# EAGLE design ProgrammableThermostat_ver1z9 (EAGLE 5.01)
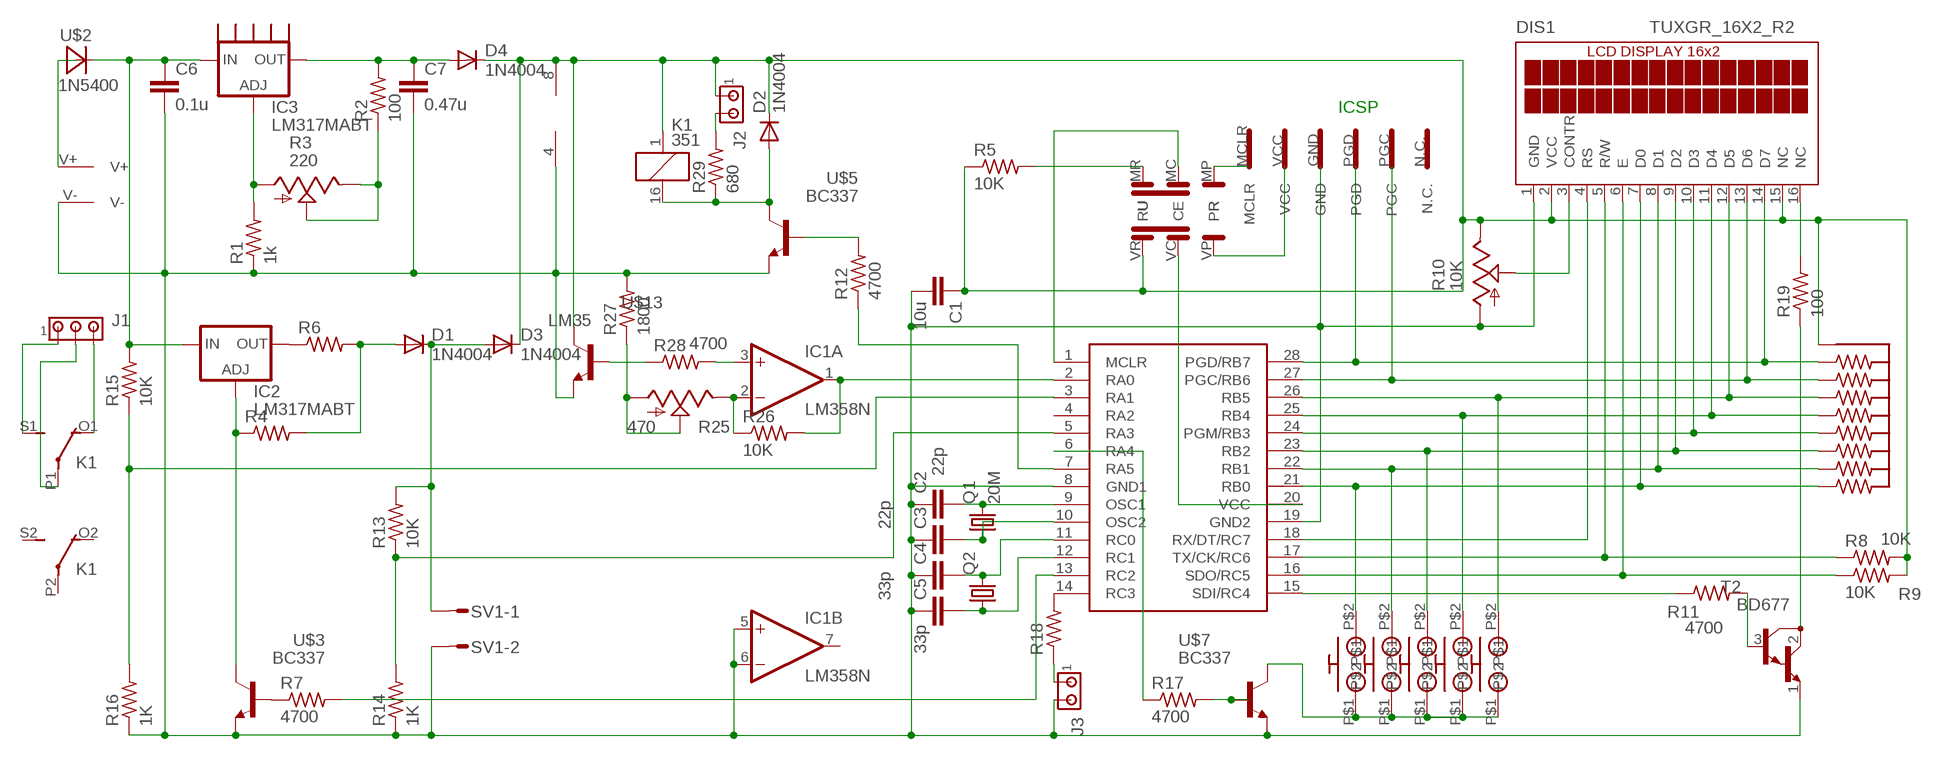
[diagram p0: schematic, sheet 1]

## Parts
C1  10u  C-EU025-050X050  [C025-050X050]
C2  22p  C-EU025-024X044  [C025-024X044]
C3  22p  C-EU025-024X044  [C025-024X044]
C4  33p  C-EU025-024X044  [C025-024X044]
C5  33p  C-EU025-024X044  [C025-024X044]
C6  0.1u  C-EU050-050X075  [C050-050X075]
C7  0.47u  C-EU050-050X075  [C050-050X075]
D1  1N4004  [DO41-10]
D2  1N4004  [DO41-10]
D3  1N4004  [DO41-10]
D4  1N4004  [DO41-10]
DIS1  TUXGR_16X2_R2  [TUXGR_16X2_R2]
IC1  LM358N  [DIL08]
IC2  LM317MABT  [TO220L1]
IC3  LM317MABT  [TO220L1]
J1  MTA03-156  [1X3MTA]
J2  MTA02-100  [10X02MTA]
J3  MTA02-100  [10X02MTA]
K1  351  [351]
Q1  20M  CRYSTALHC49U-V  [HC49U-V]
Q2  CRYSTALTC38H  [TC38H]
R1  1k  R-US_0207/7  [0207/7]
R2  100  R-US_0207/7  [0207/7]
R3  220  TRIM_US-CA9V  [CA9V]
R4  R-US_0207/7  [0207/7]
R5  10K  R-US_0207/7  [0207/7]
R6  R-US_0411/15  [0411/15]
R7  4700  R-US_0207/7  [0207/7]
R8  10K  R-US_0207/7  [0207/7]
R9  10K  R-US_0207/7  [0207/7]
R10  10K  TRIM_US-CA9V  [CA9V]
R11  4700  R-US_0207/7  [0207/7]
R12  4700  R-US_0207/7  [0207/7]
R13  10K  R-US_0207/7  [0207/7]
R14  1K  R-US_0207/7  [0207/7]
R15  10K  R-US_0207/7  [0207/7]
R16  1K  R-US_0207/7  [0207/7]
R17  4700  R-US_0207/7  [0207/7]
R18  R-US_0207/7  [0207/7]
R19  100  R-US_0207/7  [0207/7]
R25  470  TRIM_US-CA9V  [CA9V]
R26  10K  R-US_0207/7  [0207/7]
R27  1800  R-US_0207/7  [0207/7]
R28  4700  R-US_0207/7  [0207/7]
R29  680  R-US_0207/7  [0207/7]
SV1  L02P  [L02P]
T2  BD677  [TO126]
U$1  16F876A  [DIP28]
U$2  1N5400  [DO210-15]
U$3  BC337  [TO92]
U$4  SKHH  [SKHH]
U$5  BC337  [TO92]
U$6  POWER_SUPPLY  [POWER_SUPPLY]
U$7  BC337  [TO92]
U$8  SKHH  [SKHH]
U$9  HEATSINK1  [HEATSINK1]
U$10  SKHH  [SKHH]
U$11  SKHH  [SKHH]
U$12  SKHH  [SKHH]
U$13  LM35  BC337  [TO92]
U$14  ICSP  [ICSP]
U$15  ICSPSW  [ICSPSW]
U$16  RESISTIVE_NETWORK  [RESISTIVE_NETWORK_8X]

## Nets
GND: C1.2 C2.1 C3.1 C4.1 C5.1 C6.2 C7.2 DIS1.1(GND) IC1.4(P:V-) IC1.5(B:+IN) IC1.6(B:-IN) J3.2 R1.1 R10.A R14.1 R16.1 R27.2 SV1.2 T2.1(E) U$1.8(GND1) U$1.19(GND2) U$3.1(E) U$5.1(E) U$6.V- U$7.1(E) U$13.1(E) U$14.GND
N$1: R18.2 U$1.14(RC3)
N$2: C4.2 Q2.2 U$1.11(RC0)
N$3: C5.2 Q2.1 U$1.12(RC1)
N$4: IC2.1(ADJ) R4.1 U$3.3(C)
N$5: R12.1 U$1.7(RA5)
N$6: C6.1 IC2.3(IN) IC3.3(IN) R15.2 U$2.C
N$7: IC3.1(ADJ) R1.2 R3.A
N$8: R2.1 R3.E R3.S
N$9: C7.1 D4.A IC3.2(OUT) R2.2
N$10: J2.2 R29.2
N$11: U$2.A U$6.V+
N$12: IC2.2(OUT) R6.1
N$13: D1.A R4.2 R6.2
N$14: R7.1 U$3.2(B)
N$15: D1.C D3.A R13.2 SV1.1
N$16: DIS1.4(RS) U$1.18(RX/DT/RC7)
N$17: J3.1 R18.1
N$18: IC1.1(A:OUT) R26.2 U$1.2(RA0)
N$19: R15.1 R16.2 U$1.3(RA1)
N$20: R17.1 U$1.6(RA4)
N$21: R17.2 U$7.2(B)
N$22: DIS1.3(CONTR) R10.S
N$23: DIS1.7(D0) U$1.21(RB0) U$4.P$2 U$16.8
N$24: DIS1.8(D1) U$1.22(RB1) U$8.P$2 U$16.7
N$25: U$1.1(MCLR) U$15.MC(E)
N$26: U$14.MCLR U$15.MP(R)
N$27: U$14.VCC U$15.VP(PR)
N$28: R7.2 U$1.13(RC2)
N$29: R5.2 U$15.MR(U)
N$30: U$1.20(VCC) U$15.VC(C)
N$31: U$4.P$1 U$7.3(C) U$8.P$1 U$10.P$1 U$11.P$1 U$12.P$1
N$32: DIS1.14(D7) U$1.28(PGD/RB7) U$14.PGD U$16.1
N$33: DIS1.13(D6) U$1.27(PGC/RB6) U$14.PGC U$16.2
N$34: DIS1.9(D2) U$1.23(RB2) U$11.P$2 U$16.6
N$35: DIS1.10(D3) U$1.24(PGM/RB3) U$16.5
N$36: DIS1.11(D4) U$1.25(RB4) U$10.P$2 U$16.4
N$37: DIS1.12(D5) U$1.26(RB5) U$12.P$2 U$16.3
N$38: C1.1 D2.C D3.C D4.C DIS1.2(VCC) DIS1.15(NC) IC1.8(P:V+) J2.1 K1.1 R5.1 R8.2 R9.2 R10.E U$13.3(C) U$15.VR(RU) U$16.COM
N$39: DIS1.5(R/W) R8.1 U$1.17(TX/CK/RC6)
N$40: DIS1.6(E) R9.1 U$1.16(SDO/RC5)
N$41: R11.1 U$1.15(SDI/RC4)
N$42: R11.2 T2.3(B)
N$43: DIS1.16(NC) R19.2
N$44: D2.A K1.16 R29.1 U$5.3(C)
N$45: C2.2 Q1.2 U$1.9(OSC1)
N$46: C3.2 Q1.1 U$1.10(OSC2)
N$47: R12.2 U$5.2(B)
N$48: R13.1 R14.2 U$1.5(RA3)
N$49: IC1.2(A:-IN) R25.E R26.1
N$50: R25.A R25.S R27.1
N$51: R28.1 U$13.2(B)
N$52: IC1.3(A:+IN) R28.2
N$53: J1.1 K1.S1(2:S)
N$54: J1.3 K1.O1(2:O)
N$55: J1.2 K1.P1(2:P)
N$56: R19.1 T2.2(C)
Unconnected: IC1.7(B:OUT) K1.O2(3:O) K1.P2(3:P) K1.S2(3:S) U$1.4(RA2) U$14.N.C.

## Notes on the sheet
- ICSP

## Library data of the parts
C1-C7 = rcl:C-EU: CAPACITOR, European symbol
D1-D4 = diode:1N4004: DIODE
DIS1 = display-lcd:TUXGR_16X2_R2: Tuxgraphics LCD display 16x2 characters reflective, without background light Source: tuxgr_12x2_r2.pdf
IC1 = linear:LM358: OP AMP also LM158; LM258; LM2904 Source: http://cache.national.com/ds/LM/LM158.pdf
IC2 IC3 = v-reg:LM317?*: 500 mA Adjustable Output Positive Voltage Regulator Source: http://www.onsemi.co.jp .. LM317M-D.PDF
J1 = con-amp:MTA03-156: AMP connector
J2 J3 = con-amp:MTA02-100: AMP connector
K1 = relay:351: RELAY 2 x switch, Omron
Q1 Q2 = crystal:CRYSTAL: CRYSTAL
R1 R2 R4-R9 R11-R19 R26-R29 = rcl:R-US_: RESISTOR, American symbol
R3 R10 R25 = pot:TRIM_US-: POTENTIOMETER
SV1 = con-amp-mt:L02P: AMP MT CONNECTOR
T2 = transistor:BD677: NPN BIPOLAR DARLINGTON TRANSISTOR
U$1 = ciuffoli:16F876A
U$2 = ciuffoli:1N5400
U$3 U$5 U$7 U$13 = ciuffoli:BC337
U$4 U$8 U$10-U$12 = ciuffoli:SKHH
U$6 = ciuffoli:POWER_SUPPLY
U$9 = ciuffoli:HEATSINK1
U$14 = ciuffoli:ICSP
U$15 = ciuffoli:ICSPSW
U$16 = ciuffoli:RESISTIVE_NETWORK

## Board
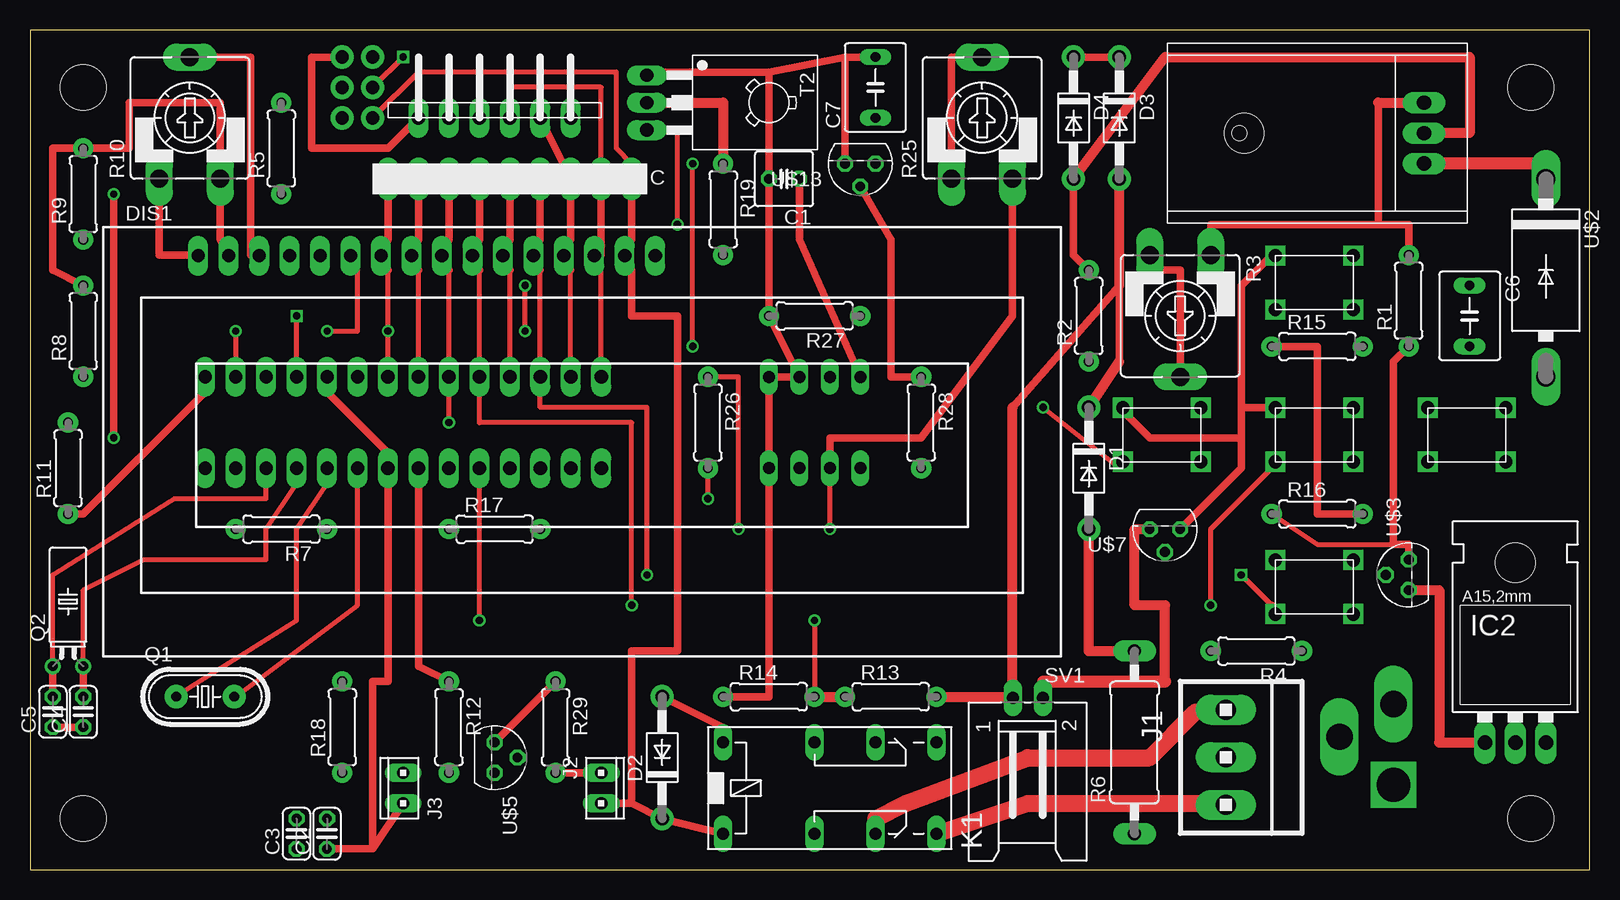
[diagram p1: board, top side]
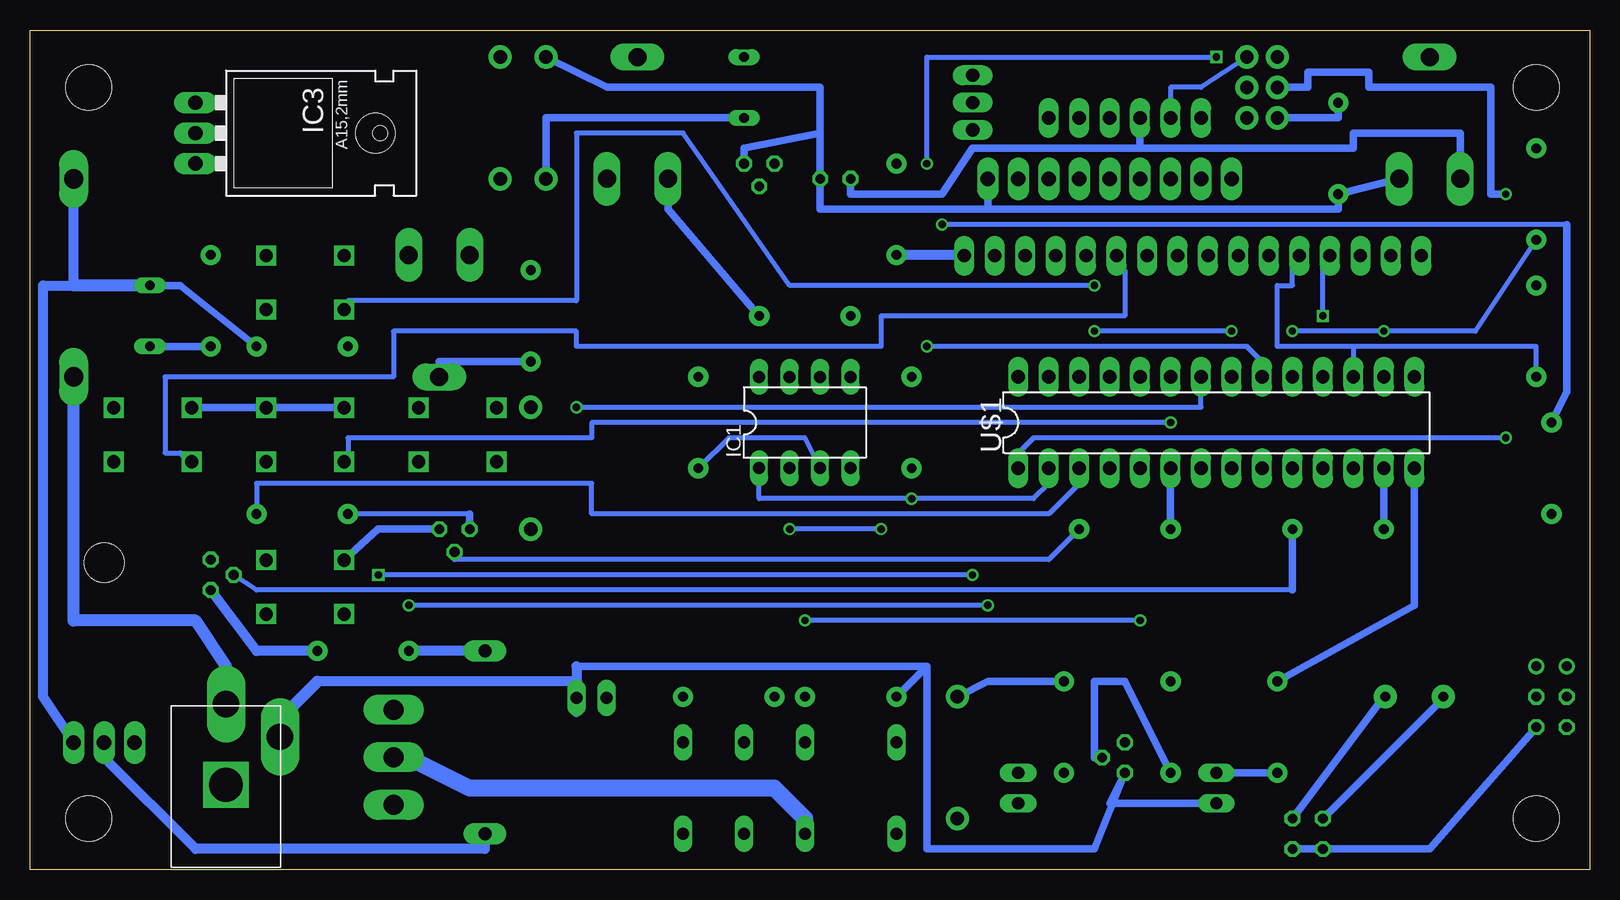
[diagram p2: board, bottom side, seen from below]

Size 130 x 70 mm. Coordinates in mm from the lower left corner, seen from the top.
Outline: 0,0 130,0 130,70 0,70 0,0
Copper layers (1*16): Top 0.035mm / dielectric 1.5mm / Bottom 0.035mm
Design rules "default": minimum track width 10mil, minimum drill 24mil, track to track 8mil, track to pad 8mil, pad to pad 8mil, via to via 8mil, smd to smd 8mil, copper to edge 40mil, drill to drill 8mil, minimum pad ring 10mil, minimum via ring 8mil, stop-mask expansion 4mil, vias tented up to drill 0mil, thermal gap 10mil
Holes 3.81 mm at 125.09,4.28 125.09,65.24 4.44,65.24 4.44,4.28

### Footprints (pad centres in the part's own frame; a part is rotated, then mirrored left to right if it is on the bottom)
C025-050X050 = drill 0.813 octagon: 1 -1.27,0; 2 1.27,0
C025-024X044 = drill 0.813 octagon: 1 -1.27,0; 2 1.27,0
C050-050X075 = drill 0.813 long: 1 -2.54,0; 2 2.54,0
DO41-10 = drill 1.118 pad 1.93 round: A 5.08,0; C -5.08,0
TUXGR_16X2_R2 = drill 1.1 pad 1.676 long: 1 -32,15.5; 2 -29.46,15.5; 3 -26.92,15.5; 4 -24.38,15.5; 5 -21.84,15.5; 6 -19.3,15.5; 7 -16.76,15.5; 8 -14.22,15.5; 9 -11.68,15.5; 10 -9.14,15.5; 11 -6.6,15.5; 12 -4.06,15.5; 13 -1.52,15.5; 14 1.02,15.5; 15 3.56,15.5; 16 6.1,15.5
DIL08 = drill 1 pad 1.422 long: 1 -3.81,-3.81; 2 -1.27,-3.81; 3 1.27,-3.81; 4 3.81,-3.81; 5 3.81,3.81; 6 1.27,3.81; 7 -1.27,3.81; 8 -3.81,3.81
TO220L1 = drill 1.2 pad 1.778 long: 1 -2.54,-3.81; 2 0,-3.81; 3 2.54,-3.81 | hole 3.302: 0,11.176
1X3MTA = drill 1.676 long: 1 3.937,0; 2 -0.025,0; 3 -3.988,0
10X02MTA = drill 1.016 long: 1 1.27,0; 2 -1.27,0
351 = drill 1.016 long: 1 -3.81,-3.81; 16 -3.81,3.81; O1 8.89,-3.81; O2 8.89,3.81; P1 3.81,-3.81; P2 3.81,3.81; S1 13.97,-3.81; S2 13.97,3.81
HC49U-V = drill 0.813 pad 1.93 round: 1 -2.413,0; 2 2.413,0
TC38H = drill 0.813 round: 1 -1.27,0; 2 1.27,0
0207/7 = drill 0.813 pad 1.676 round: 1 -3.81,0; 2 3.81,0
CA9V = drill 1.5 pad 1.93 long: A -2.54,-5.08; E 2.54,-5.08; S 0,5.08
0411/15 = drill 1.1 pad 1.778 long: 1 -7.62,0; 2 7.62,0
L02P = drill 1.016 long: 1 1.25,-6.25; 2 -1.25,-6.25
TO126 = drill 1.118 long: 1 -2.286,-5.08; 2 0,-5.08; 3 2.286,-5.08
DIP28 = drill 1.1 pad 1.422 long: 1 -15.24,-2.54; 2 -12.7,-2.54; 3 -10.16,-2.54; 4 -7.62,-2.54; 5 -5.08,-2.54; 6 -2.54,-2.54; 7 0,-2.54; 8 2.54,-2.54; 9 5.08,-2.54; 10 7.62,-2.54; 11 10.16,-2.54; 12 12.7,-2.54; 13 15.24,-2.54; 14 17.78,-2.54; 15 17.78,5.08; 16 15.24,5.08; 17 12.7,5.08; 18 10.16,5.08; 19 7.62,5.08; 20 5.08,5.08; 21 2.54,5.08; 22 0,5.08; 23 -2.54,5.08; 24 -5.08,5.08; 25 -7.62,5.08; 26 -10.16,5.08; 27 -12.7,5.08; 28 -15.24,5.08
DO210-15 = drill 1.6 pad 2.184 long: A 8.89,0; C -7.62,0
TO92 = drill 0.813 octagon: 1 1.27,0; 2 0,1.905; 3 -1.27,0
SKHH = drill 1.1 pad 1.676 square: P$1 -3.5,2.5; P$2 -3.5,-2; P$3 3,-2; P$4 3,2.5
POWER_SUPPLY = drill 2.8 pad 3.81 square: P$3 -1,0 | drill 2.2 pad 2.54 long: V+ 5.73,0; V- 3,-4.5
HEATSINK1 = hole 1.2: 0,6.5
ICSP = drill 1.1 pad 1.422 long: GND -1.27,0; MCLR -6.35,0; N.C. 6.35,0; PGC 3.81,0; PGD 1.27,0; VCC -3.81,0
ICSPSW = drill 1.1 pad 1.93 round: MC 0,1.27; MP 2.54,1.27; MR -2.54,1.27; VC 0,-1.27; VP 2.54,-1.27; VR -2.54,-1.27
RESISTIVE_NETWORK_8X = drill 1.2 pad 1.27 long: 1 -7.62,0; 2 -5.08,0; 3 -2.54,0; 4 0,0; 5 2.54,0; 6 5.08,0; 7 7.62,0; 8 10.16,0; COM -10.16,0

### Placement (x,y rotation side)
C1  62.86,57.62 180 top
C2  24.76,3.01 90 top
C3  22.22,3.01 90 top
C4  4.44,13.17 90 top
C5  1.9,13.17 90 top
C6  120.01,46.19 270 top
C7  70.48,65.24 90 top
D1  88.26,33.49 270 top
D2  52.7,9.36 90 top
D3  90.8,62.7 270 top
D4  86.99,62.7 270 top
DIS1  46.02,35.71 0 top
IC1  65.4,37.3 0 bottom
IC2  123.82,14.44 0 top
IC3  112.39,61.43 270 bottom
J1  99.69,9.36 270 top
J2  47.62,6.82 270 top
J3  31.11,6.82 90 top
K1  61.59,6.82 0 top
Q1  14.6,14.44 0 top
Q2  3.17,16.98 0 top
R1  114.93,47.46 90 top
R2  88.26,46.19 90 top
R3  95.88,46.19 180 top
R4  102.23,18.25 180 top
R5  20.95,60.16 90 top
R6  92.07,10.63 90 top
R7  20.95,28.41 180 top
R8  4.44,44.92 90 top
R9  4.44,56.35 90 top
R10  13.33,62.7 0 top
R11  3.17,33.49 90 top
R12  34.92,11.9 270 top
R13  71.75,14.44 0 top
R14  61.59,14.44 0 top
R15  107.31,43.65 0 top
R16  107.31,29.68 0 top
R17  38.73,28.41 0 top
R18  26.03,11.9 90 top
R19  57.78,55.08 270 top
R25  79.37,62.7 0 top
R26  56.51,37.3 270 top
R27  65.4,46.19 180 top
R28  74.29,37.3 270 top
R29  43.81,11.9 270 top
SV1  83.18,8.09 180 top
T2  56.51,63.97 270 top
U$1  32.38,36.03 0 bottom
U$2  126.36,50 270 top
U$3  114.93,24.6 90 top
U$4  107.31,48.73 0 top
U$5  38.73,9.36 270 top
U$6  113.66,8.09 90 bottom
U$7  94.61,28.41 180 top
U$8  94.61,36.03 0 top
U$9  107.31,61.43 90 top
U$10  120.01,36.03 0 top
U$11  107.31,36.03 0 top
U$12  107.31,23.33 0 top
U$13  69.21,58.89 180 top
U$14  38.73,62.7 0 top
U$15  27.3,65.24 90 top
U$16  40,57.62 180 top

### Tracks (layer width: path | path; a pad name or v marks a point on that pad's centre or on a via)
GND
  Top 0.254: 29.84,32.22 U$1.8 | SV1.2 84.45,15.71 | 13.33,51.27 DIS1.1
  Top 0.406: 114.93,27.14 107.31,27.14 R16.1
  Top 0.61: U$1.8 29.84,34.76 24.76,39.84 U$1.19 | C5.1 C4.1 | C2.1 28.57,1.74 | 28.57,1.74 J3.2 | 29.84,32.22 29.84,15.71 28.57,15.71 28.57,1.74 | R1.1 113.66,42.38 113.66,27.14 114.93,27.14 U$3.1 | R14.1 61.59,14.44 IC1.4 IC1.5 IC1.6 R27.2 C1.2 61.59,66.51 | 13.33,51.27 10.79,51.27 R10.A | 67.94,67.78 U$13.1 | 67.94,67.78 C7.2 | 61.59,66.51 52.7,66.51 T2.1 | 61.59,66.51 67.94,67.78
  Top 0.813: 94.61,15.71 94.61,22.06 92.07,22.06 92.07,28.41 U$7.1
  Top 1.016: 84.45,15.71 94.61,15.71
  Bottom 0.254: 84.45,13.17 SV1.2
  Bottom 0.406: 93.34,29.68 R16.1
  Bottom 0.61: J3.2 40,5.55 U$5.1 41.27,1.74 55.24,1.74 55.24,16.98 | C2.1 C3.1 13.33,1.74 C4.1 | R1.1 C6.2 | U$7.1 93.34,29.68 | 37.46,60.16 51.43,60.16 53.97,56.35 61.59,56.35 C1.2 | 37.46,60.16 U$14.GND | R10.A 10.79,61.43 19.68,61.43 19.68,60.16 37.46,60.16 | 55.24,16.98 R14.1 | 55.24,16.98 84.45,16.98
  Bottom 0.813: 84.45,15.71 106.04,15.71 | 84.45,16.98 84.45,13.17
  Bottom 1.016: 106.04,15.71 108.58,13.17 U$6.V- | SV1.2 84.45,15.71
N$1
  Bottom 0.61: R18.2 14.6,22.06 U$1.14
N$2
  Top 0.254: 22.22,32.22 U$1.11
  Top 0.406: 22.22,32.22 19.68,28.41 19.68,25.87 9.52,25.87 4.44,23.33 Q2.2
  Top 0.61: C4.2 Q2.2
N$3
  Top 0.406: Q2.1 1.9,24.6 12.06,30.95 19.68,30.95 U$1.12
  Top 0.61: C5.2 Q2.1
N$4
  Top 0.813: U$3.3 117.47,23.33 117.47,10.63 IC2.1
  Bottom 0.813: U$3.3 111.12,18.25 R4.1
N$5
  Top 0.61: U$1.7 32.38,16.98 R12.1
N$6
  Top 0.813: U$2.C 126.36,58.89
  Top 1.016: 126.36,58.89 IC3.3
  Bottom 0.61: R15.2 117.47,48.73 C6.1
  Bottom 0.813: U$2.C 126.36,48.73 128.9,48.73 128.9,14.44 IC2.3
  Bottom 1.016: C6.1 126.36,48.73
N$7
  Top 0.61: 112.39,53.81 114.93,53.81 R1.2 | 112.39,53.81 112.39,63.97 | 112.39,53.81 98.42,53.81 R3.A
  Top 0.813: 112.39,63.97 IC3.1
N$8
  Top 0.254: 93.34,50 R3.E
  Top 0.61: 93.34,50 95.88,50 R3.S
  Bottom 0.61: R2.1 95.88,42.38 R3.S
N$9
  Top 0.61: R2.2 86.99,51.27 D4.A
  Top 0.813: D4.A 94.61,67.78 120.01,67.78 120.01,61.43 IC3.2
  Bottom 0.61: D4.A 86.99,62.7 C7.1
N$10
  Top 0.61: R29.2 J2.2
N$11
  Bottom 1.016: U$2.A 126.36,20.79 116.2,20.79 113.66,16.98 U$6.V+
N$12
  Bottom 0.813: R6.1 92.07,1.74 116.2,1.74 123.82,9.36 IC2.2
N$13
  Top 0.813: D1.A 88.26,18.25 R6.2
  Bottom 0.813: R6.2 R4.2
N$14
  Bottom 0.406: 24.76,23.33 111.12,23.33 U$3.2
  Bottom 0.61: 24.76,23.33 R7.1
N$15
  Top 0.254: 81.91,14.44 SV1.1 81.91,15.71
  Top 0.61: 90.8,42.38 90.8,48.73 81.91,38.57
  Top 0.813: R13.2 81.91,14.44 | 90.8,42.38 D1.C | 90.8,48.73 D3.A | 81.91,15.71 81.91,38.57
N$16  (via drill 0.6)
  Top 0.406: U$1.18 v22.22,46.19
  Bottom 0.254: 22.22,51.27 DIS1.4
  Bottom 0.406: v22.22,46.19 22.22,51.27
N$17
  Bottom 0.61: R18.1 J3.1
N$18  (via drill 0.61)
  Top 0.406: v56.51,30.95 R26.2
  Bottom 0.254: 45.08,32.22 U$1.2
  Bottom 0.406: 45.08,32.22 46.35,30.95 v56.51,30.95 69.21,30.95 IC1.1
N$19
  Top 0.61: R15.1 107.31,43.65 107.31,29.68 R16.2
  Bottom 0.254: 42.54,32.22 U$1.3
  Bottom 0.406: 42.54,32.22 45.08,29.68 83.18,29.68 83.18,32.22 111.12,32.22 R16.2
N$20
  Bottom 0.61: R17.1 U$1.6
N$21
  Bottom 0.254: 94.61,25.87 U$7.2
  Bottom 0.406: 94.61,25.87 45.08,25.87 R17.2
N$22
  Top 0.254: DIS1.3 18.41,51.27 | 14.6,67.78 R10.S
  Top 0.61: 18.41,51.27 18.41,67.78 14.6,67.78
N$23  (via drill 0.6, 0.61)
  Top 0.406: v41.27,44.92 v41.27,48.73 | U$1.21 v29.84,44.92 29.84,50
  Top 0.61: U$16.8 29.84,52.54 DIS1.7 29.84,50
  Bottom 0.254: 103.5,47.46 U$4.P$2
  Bottom 0.406: 103.5,47.46 84.45,47.46 84.45,61.43 75.56,61.43 66.67,48.73 v41.27,48.73 | v29.84,44.92 v41.27,44.92
N$24  (via drill 0.61)
  Top 0.254: 90.8,33.49 U$8.P$2
  Top 0.406: v84.45,38.57 90.8,33.49 | U$1.22 32.38,50
  Top 0.61: U$16.7 32.38,52.54 DIS1.8 32.38,50
  Bottom 0.406: v84.45,38.57 32.38,38.57 U$1.22
N$25  (via drill 0.61)
  Top 0.61: v6.98,36.03 v6.98,56.35
  Bottom 0.254: 47.62,34.76 U$1.1
  Bottom 0.406: 47.62,34.76 46.35,36.03 v6.98,36.03
  Bottom 0.61: v6.98,56.35 8.25,56.35 8.25,65.24 18.41,65.24 18.41,66.51 23.49,66.51 23.49,65.24 U$15.MC
N$26
  Top 0.61: U$14.MCLR 29.84,60.16 23.49,60.16 23.49,67.78 U$15.MP
N$27
  Bottom 0.406: U$15.VP 32.38,65.24 34.92,65.24 U$14.VCC
N$28
  Bottom 0.61: R7.2 U$1.13
N$29  (via drill 0.61)
  Bottom 0.61: R5.2 20.95,62.7 U$15.MR
  other vias: 20.95,63.97
N$30  (via drill 0.6, 0.61)
  Top 0.406: v55.24,43.65 v55.24,58.89 | v31.11,67.78 U$15.VC
  Bottom 0.406: v55.24,43.65 28.57,43.65 27.3,42.38 U$1.20 | v55.24,58.89 55.24,67.78 v31.11,67.78
N$31
  Top 0.254: 90.8,38.57 U$8.P$1 | 103.5,38.57 U$11.P$1 | 103.5,51.27 U$4.P$1
  Top 0.61: 90.8,38.57 93.34,36.03 100.96,36.03 | 100.96,38.57 103.5,38.57 | 100.96,36.03 100.96,33.49 U$7.3 | 100.96,36.03 100.96,38.57 | 103.5,51.27 100.96,48.73 100.96,38.57
  Bottom 0.254: 116.2,38.57 U$10.P$1 | U$11.P$1 103.5,38.57
  Bottom 0.61: U$7.3 100.96,28.41 U$12.P$1 | 103.5,38.57 116.2,38.57
N$32
  Top 0.254: 40,65.24 U$14.PGD | 47.62,51.27 DIS1.14
  Top 0.406: U$1.28 47.62,51.27 | 40,65.24 47.62,65.24 U$16.1
  Top 0.61: 47.62,51.27 U$16.1
N$33
  Top 0.406: U$1.27 45.08,50
  Top 0.61: U$14.PGC U$16.2 45.08,52.54 DIS1.13 45.08,50
N$34  (via drill 0.61)
  Top 0.406: 34.92,50 U$1.23 v34.92,37.3 34.92,38.57
  Top 0.61: U$16.6 34.92,52.54 DIS1.9 34.92,50
  Bottom 0.254: 103.5,34.76 U$11.P$2
  Bottom 0.406: 103.5,34.76 103.5,36.03 83.18,36.03 83.18,37.3 v34.92,37.3
  other vias: 34.92,41.11 34.92,41.11
N$35  (via drill 0.61)
  Top 0.406: 37.46,50 U$1.24 37.46,37.3 50.16,37.3 v50.16,22.06 | 103.5,33.49 98.42,28.41 v98.42,22.06
  Top 0.61: 37.46,50 DIS1.10 37.46,52.54 U$16.5
  Bottom 0.406: v50.16,22.06 v98.42,22.06
N$36
  Top 0.406: U$1.25 40,50
  Top 0.61: 40,50 DIS1.11 40,52.54 U$16.4
  Bottom 0.254: DIS1.11 38.73,50 | 116.2,33.49 U$10.P$2
  Bottom 0.406: 116.2,33.49 117.47,34.76 118.74,34.76 118.74,41.11 99.69,41.11 99.69,44.92 84.45,44.92 84.45,43.65 59.05,43.65 59.05,46.19 38.73,46.19 38.73,50
N$37  (via drill 0.6, 0.61)
  Top 0.406: v100.96,24.6 103.5,22.06 | v51.43,24.6 51.43,38.57 42.54,38.57 U$1.26 42.54,50
  Top 0.61: U$16.3 42.54,52.54 DIS1.12 42.54,50 | 103.5,22.06 U$12.P$2
  Bottom 0.406: v51.43,24.6 v100.96,24.6
N$38
  Top 0.254: U$16.COM 50.16,58.89
  Top 0.406: U$15.VR 32.38,66.51 48.89,66.51 48.89,60.16 50.16,58.89
  Top 0.61: D4.C D3.C | C1.1 64.13,52.54 IC1.8 | R8.2 1.9,50 1.9,60.16 R9.2 8.25,60.16 8.25,63.97 15.87,63.97 R10.E 15.87,52.54 DIS1.2 | K1.1 D2.C 50.16,5.55 | U$16.COM 50.16,52.54 DIS1.15 50.16,50 50.16,46.19 53.97,46.19 53.97,18.25 50.16,18.25 50.16,5.55 | 50.16,5.55 J2.1
  Bottom 0.61: U$13.3 70.48,60.16 64.13,61.43 | 64.13,61.43 C1.1 64.13,55.08 50.16,55.08 | D4.C 81.91,65.24 64.13,65.24 64.13,61.43 | R10.E R5.1 20.95,55.08 50.16,55.08 | 50.16,55.08 U$16.COM
N$39
  Bottom 0.254: 24.76,51.27 DIS1.5
  Bottom 0.406: 19.68,43.65 26.03,43.65 26.03,48.73 24.76,48.73 24.76,51.27 | 19.68,43.65 U$1.17 | R8.1 4.44,43.65 19.68,43.65
N$40  (via drill 0.6)
  Top 0.254: 27.3,51.27 DIS1.6 | 17.14,42.38 U$1.16
  Top 0.406: v17.14,44.92 17.14,42.38 | v24.76,44.92 27.3,44.92 27.3,51.27
  Bottom 0.406: R9.1 9.52,44.92 v17.14,44.92 v24.76,44.92
N$41
  Top 0.61: R11.1 4.44,29.68 14.6,39.84 U$1.15
N$42  (via drill 0.61)
  Top 0.254: 53.97,61.43 53.97,61.68
  Top 0.406: v53.97,53.81 53.97,61.43 T2.3 53.97,61.68
  Bottom 0.406: 1.9,53.81 v53.97,53.81
  Bottom 0.61: R11.2 1.9,39.84 1.9,53.81
N$43
  Bottom 0.254: DIS1.16 52.7,51.27
  Bottom 0.813: 52.7,51.27 R19.2
N$44
  Top 0.254: 57.78,11.9 K1.16
  Top 0.61: D2.A 57.78,11.9 | U$5.3 R29.1
  Bottom 0.61: D2.A 50.16,15.71 R29.1
N$45  (via drill 0.6)
  Top 0.254: v17.14,14.44 Q1.2
  Top 0.406: v17.14,14.44 27.3,22.06 U$1.9
  Bottom 0.61: C2.2 v17.14,14.44
N$46  (via drill 0.6)
  Top 0.254: 24.76,32.22 U$1.10 | v12.06,14.44 Q1.1
  Top 0.406: 24.76,32.22 22.22,28.41 22.22,20.79 v12.06,14.44
  Bottom 0.61: C3.2 v12.06,14.44
N$47
  Bottom 0.61: R12.2 38.73,15.71 41.27,15.71 41.27,9.36 U$5.2
N$48  (via drill 0.6)
  Top 0.406: v65.4,20.79 R14.2 | v37.46,20.79 U$1.5
  Top 0.813: R14.2 R13.1
  Bottom 0.406: v37.46,20.79 v65.4,20.79
N$49  (via drill 0.6)
  Top 0.406: R26.1 59.05,41.11 v59.05,28.41 | v66.67,28.41 IC1.2
  Top 0.61: IC1.2 66.67,36.03 74.29,36.03 81.91,46.19 R25.E
  Bottom 0.406: v59.05,28.41 v66.67,28.41
N$50
  Top 0.61: R25.S 76.83,67.78 R25.A
  Bottom 0.61: R27.1 76.83,55.08 R25.A
N$51
  Top 0.61: R28.1 71.75,41.11 71.75,52.54 U$13.2
N$52
  Bottom 0.406: IC1.3 65.4,36.03 71.75,36.03 R28.2
N$53
  Top 0.254: 99.69,5.55 J1.1
  Top 1.422: 99.69,5.55 83.18,5.55 K1.S1
N$54
  Top 0.254: K1.O1 70.48,4.28
  Top 1.016: 97.15,13.17 J1.3
  Top 1.422: 70.48,4.28 73.02,5.55 83.18,9.36 93.34,9.36 97.15,13.17
N$55
  Bottom 0.254: K1.P1 65.4,4.28 | 98.42,9.36 J1.2
  Bottom 1.422: 65.4,4.28 67.94,6.82 93.34,6.82 98.42,9.36
N$56
  Top 0.813: R19.1 57.78,63.97 T2.2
